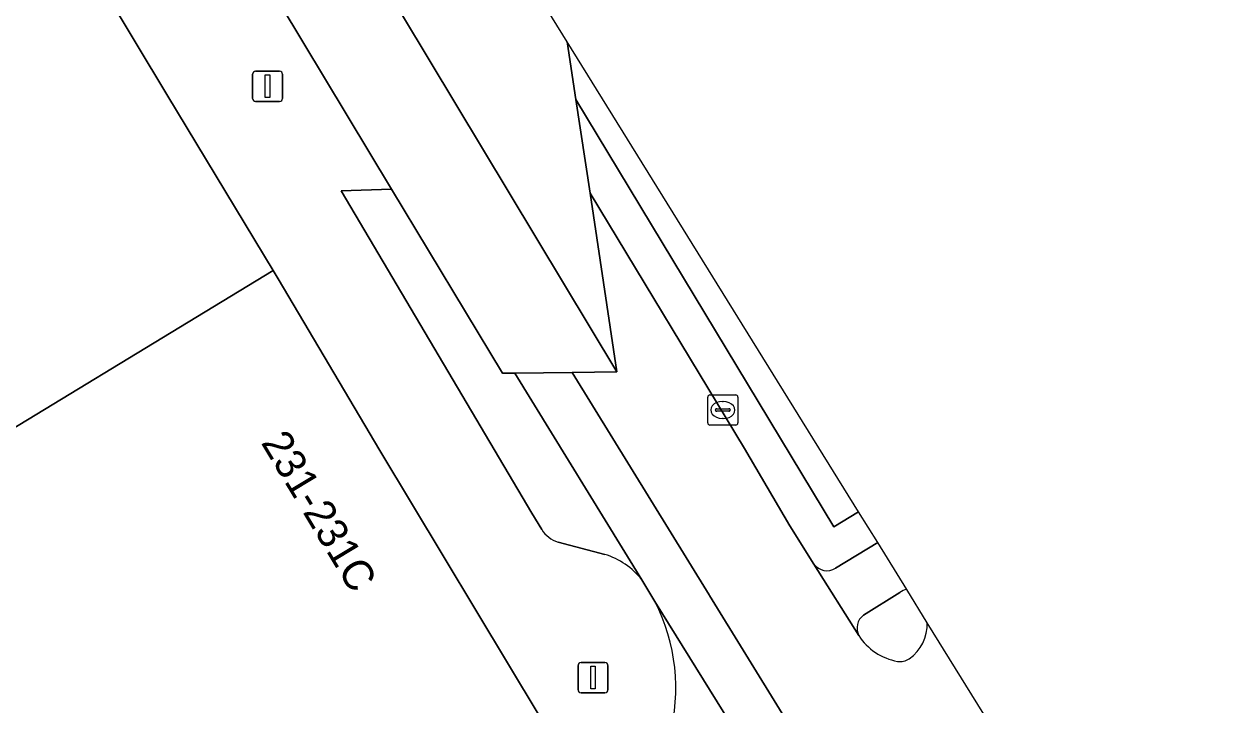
# Model space of a CAD drawing. Extents: x 159888 to 160761, y 384031 to 384750.
# Drawn here: x 160503.27 to 160543.15, y 384483.01 to 384505.51 of the extents above; entities that cross this region are included whole.
import ezdxf

# ---------------------------------------------------------------- set-up
doc = ezdxf.new("R2010")
doc.units = 0
for name, color, linetype in [('IMGEO_Berm_groen', 7, 'Continuous'), ('IMGEO_Fietspad_gesloten', 7, 'Continuous'), ('IMGEO_Kolk', 7, 'Continuous'), ('IMGEO_Lichtmast', 7, 'Continuous'), ('IMGEO_Oever', 7, 'Continuous'), ('IMGEO_Pand', 7, 'Continuous'), ('IMGEO_Pand_nummerreeks', 7, 'Continuous'), ('IMGEO_Parkeervlak_open', 7, 'Continuous'), ('IMGEO_Rijbaan_lokaal_gesloten', 7, 'Continuous'), ('IMGEO_Verkeerseiland_open', 7, 'Continuous'), ('IMGEO_Voetpad_open', 7, 'Continuous')]:
    doc.layers.add(name, color=color, linetype=linetype)

msp = doc.modelspace()

# ---------------------------------------------------------------- linework, layer by layer
at = {"layer": 'IMGEO_Berm_groen'}
msp.add_lwpolyline([(160521.234, 384504.924), (160521.52, 384503.02), (160530.053, 384488.897), (160530.865, 384489.393)], close=True, dxfattribs=at)
for points in [[(160531.499, 384488.371), (160530.865, 384489.393), (160530.053, 384488.897), (160521.52, 384503.02), (160521.986, 384499.927), (160527.089, 384491.477), (160528.599, 384488.928), (160529.392, 384487.663)], [(160530.103, 384487.524), (160531.499, 384488.371)]]:
    msp.add_lwpolyline(points, dxfattribs=at)
msp.add_arc((160529.82, 384487.964), 0.523, 215.0927, 302.7838, dxfattribs=at)
at = {"layer": 'IMGEO_Fietspad_gesloten'}
msp.add_lwpolyline([(160477.316, 384563.328), (160515.425, 384500.053), (160519.088, 384493.971), (160519.494, 384493.976), (160521.397, 384493.999), (160522.875, 384494.017), (160482.029, 384561.886), (160478.437, 384567.605), (160475.465, 384570.046)], dxfattribs=at)
at = {"layer": 'IMGEO_Kolk'}
for p, q in [((160525.877, 384492.329), (160525.877, 384493.181)), ((160525.952, 384493.255), (160526.804, 384493.255)), ((160526.365, 384493.035), (160526.39, 384493.035)), ((160526.878, 384493.181), (160526.878, 384492.329)), ((160526.136, 384492.749), (160526.136, 384492.761)), ((160526.574, 384492.712), (160526.176, 384492.712)), ((160526.179, 384492.798), (160526.577, 384492.798)), ((160526.62, 384492.761), (160526.62, 384492.749)), ((160526.804, 384492.255), (160525.952, 384492.255)), ((160526.388, 384492.475), (160526.363, 384492.475))]:
    msp.add_line(p, q, dxfattribs=at)
for points in [[(160525.877, 384492.329), (160525.877, 384493.181)], [(160525.952, 384493.255), (160526.804, 384493.255)], [(160526.878, 384493.181), (160526.878, 384492.329)], [(160526.804, 384492.255), (160525.952, 384492.255)]]:
    msp.add_lwpolyline(points, dxfattribs=at)
for centre, radius, start, end in [((160525.954, 384493.179), 0.0765, 91.552, 178.448), ((160525.954, 384493.179), 0.0765, 91.552, 178.448), ((160526.802, 384493.179), 0.0765, 1.552, 88.448), ((160526.802, 384493.179), 0.0765, 1.552, 88.448), ((160526.176, 384492.758), 0.0403, 85.8775, 175.7526), ((160526.173, 384492.748), 0.0366, 178.938, 274.7102), ((160526.577, 384492.755), 0.043, 264.8664, 352.4533), ((160526.581, 384492.76), 0.0386, 1.7309, 96.639), ((160525.954, 384492.331), 0.0765, 181.552, 268.448), ((160525.954, 384492.331), 0.0765, 181.552, 268.448), ((160526.802, 384492.331), 0.0765, 271.552, 358.448), ((160526.802, 384492.331), 0.0765, 271.552, 358.448)]:
    msp.add_arc(centre, radius, start, end, dxfattribs=at)
for centre, major_axis, ratio, start_param, end_param in [((160526.364, 384492.755), (-0.387, 0.002), 0.722429, 4.712389, 7.853982), ((160526.389, 384492.755), (-0.39, 0.002), 0.717154, 1.570796, 4.712389)]:
    msp.add_ellipse(centre, major_axis=major_axis, ratio=ratio, start_param=start_param, end_param=end_param, dxfattribs=at)
at = {"layer": 'IMGEO_Lichtmast'}
for p, q in [((160510.827, 384503.056), (160510.827, 384503.856)), ((160510.827, 384503.856), (160510.827, 384503.056)), ((160510.927, 384503.956), (160511.717, 384503.956)), ((160511.717, 384503.956), (160510.927, 384503.956)), ((160511.817, 384503.856), (160511.817, 384503.056)), ((160511.817, 384503.056), (160511.817, 384503.856)), ((160511.717, 384502.956), (160510.927, 384502.956)), ((160510.927, 384502.956), (160511.717, 384502.956)), ((160521.59, 384483.508), (160521.59, 384484.308)), ((160521.59, 384484.308), (160521.59, 384483.508)), ((160521.69, 384484.408), (160522.48, 384484.408)), ((160522.48, 384484.408), (160521.69, 384484.408)), ((160522.58, 384484.308), (160522.58, 384483.508)), ((160522.58, 384483.508), (160522.58, 384484.308)), ((160522.48, 384483.408), (160521.69, 384483.408)), ((160521.69, 384483.408), (160522.48, 384483.408))]:
    msp.add_line(p, q, dxfattribs=at)
for points in [[(160511.247, 384503.831), (160511.397, 384503.831), (160511.397, 384503.081), (160511.247, 384503.081), (160511.247, 384503.831)], [(160522.01, 384484.283), (160522.16, 384484.283), (160522.16, 384483.533), (160522.01, 384483.533), (160522.01, 384484.283)]]:
    msp.add_lwpolyline(points, dxfattribs=at)
for centre, start, end in [((160510.927, 384503.856), 90, 180), ((160510.927, 384503.856), 90, 180), ((160511.717, 384503.856), 0, 90), ((160511.717, 384503.856), 360, 90), ((160510.927, 384503.056), 180, 270), ((160510.927, 384503.056), 180, 270), ((160511.717, 384503.056), 270, 0), ((160511.717, 384503.056), 270, 0), ((160521.69, 384484.308), 90, 180), ((160521.69, 384484.308), 90, 180), ((160522.48, 384484.308), 0, 90), ((160522.48, 384484.308), 360, 90), ((160521.69, 384483.508), 180, 270), ((160521.69, 384483.508), 180, 270), ((160522.48, 384483.508), 270, 0), ((160522.48, 384483.508), 270, 0)]:
    msp.add_arc(centre, 0.1, start, end, dxfattribs=at)
at = {"layer": 'IMGEO_Oever'}
msp.add_lwpolyline([(160479.191, 384569.818), (160477.984, 384571.604), (160475.465, 384570.046), (160478.437, 384567.605), (160482.029, 384561.886), (160522.875, 384494.017), (160521.986, 384499.927), (160521.52, 384503.02), (160521.234, 384504.924), (160505.019, 384531.072), (160500.777, 384538.881)], dxfattribs=at)
at = {"layer": 'IMGEO_Pand'}
for points in [[(160497.134, 384521.348), (160487.673, 384515.164), (160484.383, 384512.721), (160484.643, 384512.292), (160492.11, 384500), (160498.504, 384489.473), (160500, 384490.382), (160511.508, 384497.372), (160508.017, 384503.132), (160504.816, 384508.47), (160501.628, 384513.801), (160497.396, 384520.838)], [(160520.333, 384482.605), (160515.038, 384491.416), (160511.677, 384497.092), (160511.508, 384497.372), (160500, 384490.382), (160498.504, 384489.473), (160498.593, 384489.327), (160494.833, 384487.044), (160495.493, 384485.697), (160497.552, 384481.492), (160496.917, 384481.107), (160498.809, 384477.059), (160500, 384474.509), (160500.925, 384472.529), (160511.409, 384477.481), (160511.574, 384477.21)]]:
    msp.add_lwpolyline(points, close=True, dxfattribs=at)
at = {"layer": 'IMGEO_Parkeervlak_open'}
for points in [[(160519.494, 384493.976), (160519.088, 384493.971), (160515.425, 384500.053), (160513.754, 384500), (160520.062, 384489.344), (160520.388, 384488.803)], [(160523.701, 384487.143), (160519.494, 384493.976)], [(160520.93, 384488.385), (160522.473, 384487.982)]]:
    msp.add_lwpolyline(points, dxfattribs=at)
for centre, radius, start, end in [((160521.261, 384489.375), 1.044, 213.2194, 251.5005), ((160521.715, 384485.554), 2.544, 38.6618, 72.6545)]:
    msp.add_arc(centre, radius, start, end, dxfattribs=at)
at = {"layer": 'IMGEO_Rijbaan_lokaal_gesloten'}
for points in [[(160530.872, 384485.299), (160529.392, 384487.663), (160528.599, 384488.928), (160527.089, 384491.477), (160521.986, 384499.927), (160522.875, 384494.017), (160521.397, 384493.999), (160525.927, 384486.643), (160525.936, 384486.628), (160565.675, 384422.118), (160628.254, 384321.427), (160631.369, 384323.299), (160615.861, 384348.269), (160564.541, 384431.158), (160546.729, 384459.74), (160546.003, 384460.9), (160545.604, 384461.675)], [(160537.564, 384464.718), (160537.603, 384464.743), (160524.133, 384486.422)], [(160544.042, 384468.144), (160540.777, 384473.409), (160533.14, 384485.724)]]:
    msp.add_lwpolyline(points, dxfattribs=at)
msp.add_lwpolyline([(160525.936, 384486.628), (160525.927, 384486.643), (160521.397, 384493.999), (160519.494, 384493.976), (160523.701, 384487.143), (160524.133, 384486.422), (160537.603, 384464.743), (160543.713, 384454.868), (160591.404, 384377.897), (160615.758, 384338.612), (160624.721, 384324.154), (160626.898, 384320.642), (160628.254, 384321.427), (160565.675, 384422.118)], close=True, dxfattribs=at)
for centre, radius, start, end in [((160518.526, 384483.556), 6.297, 345.3793, 27.0724), ((160531.746, 384485.679), 1.395, 304.747, 1.8579), ((160532.509, 384486.366), 1.954, 213.0956, 259.483), ((160532.235, 384484.983), 0.544, 261.2479, 304.246)]:
    msp.add_arc(centre, radius, start, end, dxfattribs=at)
at = {"layer": 'IMGEO_Verkeerseiland_open'}
for points in [[(160532.23, 384486.723), (160531.031, 384485.977)], [(160533.14, 384485.724), (160532.461, 384486.819)]]:
    msp.add_lwpolyline(points, dxfattribs=at)
for centre, radius, start, end in [((160532.511, 384486.375), 0.447, 96.3703, 128.9008), ((160531.365, 384485.541), 0.549, 127.4694, 206.1343), ((160531.746, 384485.679), 1.395, 304.747, 1.8579), ((160532.509, 384486.366), 1.954, 213.0956, 259.483), ((160532.235, 384484.983), 0.544, 261.2479, 304.246)]:
    msp.add_arc(centre, radius, start, end, dxfattribs=at)
at = {"layer": 'IMGEO_Voetpad_open'}
for points in [[(160520.388, 384488.803), (160520.062, 384489.344), (160513.754, 384500), (160515.425, 384500.053), (160477.316, 384563.328)], [(160504.816, 384508.47), (160508.017, 384503.132), (160511.508, 384497.372), (160511.677, 384497.092), (160515.038, 384491.416), (160520.333, 384482.605), (160522.776, 384478.582)], [(160522.473, 384487.982), (160520.93, 384488.385)], [(160532.461, 384486.819), (160531.499, 384488.371), (160530.103, 384487.524)], [(160529.392, 384487.663), (160530.872, 384485.299)], [(160524.133, 384486.422), (160523.701, 384487.143)], [(160531.031, 384485.977), (160532.23, 384486.723)]]:
    msp.add_lwpolyline(points, dxfattribs=at)
for centre, radius, start, end in [((160521.261, 384489.375), 1.044, 213.2194, 251.5005), ((160521.715, 384485.554), 2.544, 38.6618, 72.6545), ((160529.82, 384487.964), 0.523, 215.0927, 302.7838), ((160532.511, 384486.375), 0.447, 96.3703, 128.9008), ((160518.526, 384483.556), 6.297, 345.3793, 27.0724), ((160531.365, 384485.541), 0.549, 127.4694, 206.1343)]:
    msp.add_arc(centre, radius, start, end, dxfattribs=at)

# ---------------------------------------------------------------- texts
at = {"layer": 'IMGEO_Pand_nummerreeks'}
msp.add_text('231-231C', height=1, rotation=301.1057, dxfattribs=at).set_placement((160511.086, 384491.675))

doc.saveas('drawing.dxf')
